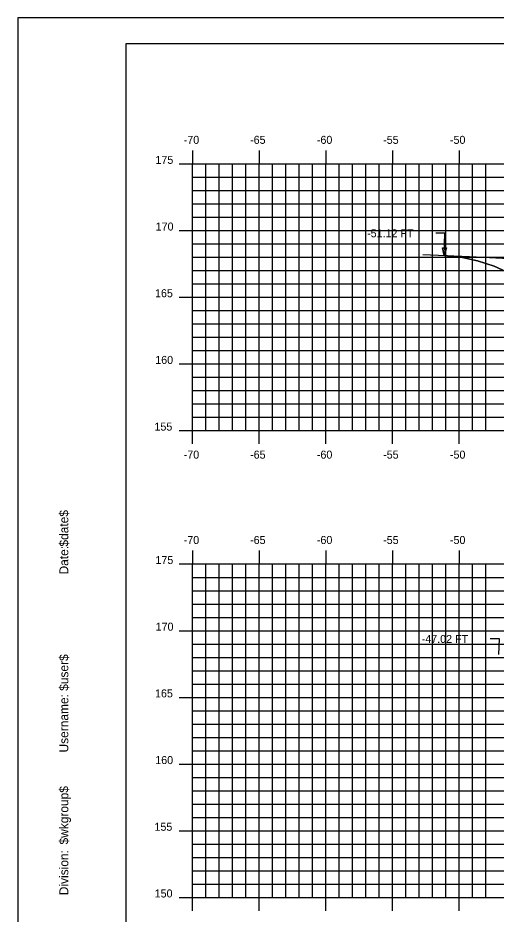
# Model space of a CAD drawing. Extents: x 1141424 to 1141594, y 608981 to 609091.
# Drawn here: x 1141424.2 to 1141460, y 609024.1 to 609091.3 of the extents above; entities that cross this region are included whole.
import ezdxf

# ---------------------------------------------------------------- set-up
doc = ezdxf.new("R2010")
doc.units = 0
for name, color, linetype in [('BORDER', 7, 'Continuous'), ('D_Roadway_SlopeLines', 7, 'Continuous'), ('D_Text_Standard', 7, 'Continuous'), ('H_V ANNOTATION', 7, 'Continuous'), ('MAJOR', 7, 'Continuous'), ('MINOR', 7, 'Continuous'), ('PLOT BOUNDARY', 7, 'Continuous'), ('S_Roadway_Centerline', 7, 'Continuous')]:
    doc.layers.add(name, color=color, linetype=linetype)

msp = doc.modelspace()

# ---------------------------------------------------------------- linework, layer by layer
msp.add_lwpolyline([(1141456.146, 609073.465), (1141457.396, 609073.337), (1141458.646, 609073.068), (1141459.896, 609072.656), (1141461.146, 609072.102), (1141473.145, 609066.102), (1141476.145, 609067.102), (1141483.295, 609069.486), (1141483.296, 609069.486), (1141496.271, 609070.005), (1141507.271, 609070.225), (1141518.271, 609070.005), (1141522.271, 609069.845), (1141529.994, 609067.271), (1141532.994, 609066.271), (1141540.103, 609069.825), (1141541.353, 609070.365), (1141542.603, 609070.736), (1141543.853, 609070.937), (1141545.103, 609070.968)])
at = {"layer": 'BORDER'}
msp.add_lwpolyline([(1141432.271, 608984.335), (1141592.271, 608984.335), (1141592.271, 609089.335), (1141432.271, 609089.335)], close=True, dxfattribs=at)
at = {"layer": 'D_Roadway_SlopeLines'}
msp.add_lwpolyline([(1141473.145, 609066.102), (1141461.146, 609072.102), (1141459.896, 609072.656), (1141458.646, 609073.068), (1141457.396, 609073.337), (1141456.146, 609073.465)], dxfattribs=at)
at = {"layer": 'D_Text_Standard'}
for points in [[(1141456.146, 609073.465), (1141456.186, 609075.131), (1141455.506, 609075.131)], [(1141460.253, 609043.541), (1141460.282, 609044.715), (1141459.602, 609044.715)]]:
    msp.add_lwpolyline(points, dxfattribs=at)
msp.add_lwpolyline([(1141456.146, 609073.465), (1141456.015, 609074.05), (1141456.306, 609074.043)], close=True, dxfattribs=at)
at = {"layer": 'MAJOR'}
for p, q in [((1141437.271, 609081.337), (1141437.271, 609080.335)), ((1141442.271, 609081.337), (1141442.271, 609080.335)), ((1141447.271, 609081.337), (1141447.271, 609080.335)), ((1141452.271, 609081.337), (1141452.271, 609080.335)), ((1141457.271, 609081.337), (1141457.271, 609080.335)), ((1141436.269, 609080.335), (1141437.271, 609080.335)), ((1141437.271, 609080.335), (1141577.271, 609080.335)), ((1141437.271, 609060.335), (1141437.271, 609080.335)), ((1141437.271, 609060.335), (1141437.271, 609080.335)), ((1141437.271, 609080.335), (1141577.271, 609080.335)), ((1141442.271, 609060.335), (1141442.271, 609080.335)), ((1141447.271, 609060.335), (1141447.271, 609080.335)), ((1141452.271, 609060.335), (1141452.271, 609080.335)), ((1141457.271, 609060.335), (1141457.271, 609080.335)), ((1141436.269, 609075.335), (1141437.271, 609075.335)), ((1141437.271, 609075.335), (1141577.271, 609075.335)), ((1141436.269, 609070.335), (1141437.271, 609070.335)), ((1141437.271, 609070.335), (1141577.271, 609070.335)), ((1141436.269, 609065.335), (1141437.271, 609065.335)), ((1141437.271, 609065.335), (1141577.271, 609065.335)), ((1141436.269, 609060.335), (1141437.271, 609060.335)), ((1141437.271, 609060.335), (1141577.271, 609060.335)), ((1141437.271, 609060.335), (1141577.271, 609060.335)), ((1141437.271, 609059.333), (1141437.271, 609060.335)), ((1141442.271, 609059.333), (1141442.271, 609060.335)), ((1141447.271, 609059.333), (1141447.271, 609060.335)), ((1141452.271, 609059.333), (1141452.271, 609060.335)), ((1141457.271, 609059.333), (1141457.271, 609060.335)), ((1141437.271, 609051.337), (1141437.271, 609050.335)), ((1141442.271, 609051.337), (1141442.271, 609050.335)), ((1141447.271, 609051.337), (1141447.271, 609050.335)), ((1141452.271, 609051.337), (1141452.271, 609050.335)), ((1141457.271, 609051.337), (1141457.271, 609050.335)), ((1141436.269, 609050.335), (1141437.271, 609050.335)), ((1141437.271, 609050.335), (1141577.271, 609050.335)), ((1141437.271, 609025.335), (1141437.271, 609050.335)), ((1141437.271, 609025.335), (1141437.271, 609050.335)), ((1141437.271, 609050.335), (1141577.271, 609050.335)), ((1141442.271, 609025.335), (1141442.271, 609050.335)), ((1141447.271, 609025.335), (1141447.271, 609050.335)), ((1141452.271, 609025.335), (1141452.271, 609050.335)), ((1141457.271, 609025.335), (1141457.271, 609050.335)), ((1141436.269, 609045.335), (1141437.271, 609045.335)), ((1141437.271, 609045.335), (1141577.271, 609045.335)), ((1141436.269, 609040.335), (1141437.271, 609040.335)), ((1141437.271, 609040.335), (1141577.271, 609040.335)), ((1141436.269, 609035.335), (1141437.271, 609035.335)), ((1141437.271, 609035.335), (1141577.271, 609035.335)), ((1141436.269, 609030.335), (1141437.271, 609030.335)), ((1141437.271, 609030.335), (1141577.271, 609030.335)), ((1141436.269, 609025.335), (1141437.271, 609025.335)), ((1141437.271, 609025.335), (1141577.271, 609025.335)), ((1141437.271, 609025.335), (1141577.271, 609025.335)), ((1141437.271, 609024.333), (1141437.271, 609025.335)), ((1141442.271, 609024.333), (1141442.271, 609025.335)), ((1141447.271, 609024.333), (1141447.271, 609025.335)), ((1141452.271, 609024.333), (1141452.271, 609025.335)), ((1141457.271, 609024.333), (1141457.271, 609025.335))]:
    msp.add_line(p, q, dxfattribs=at)
at = {"layer": 'MINOR'}
for p, q in [((1141438.271, 609060.335), (1141438.271, 609080.335)), ((1141439.271, 609060.335), (1141439.271, 609080.335)), ((1141440.271, 609060.335), (1141440.271, 609080.335)), ((1141441.271, 609060.335), (1141441.271, 609080.335)), ((1141443.271, 609060.335), (1141443.271, 609080.335)), ((1141444.271, 609060.335), (1141444.271, 609080.335)), ((1141445.271, 609060.335), (1141445.271, 609080.335)), ((1141446.271, 609060.335), (1141446.271, 609080.335)), ((1141448.271, 609060.335), (1141448.271, 609080.335)), ((1141449.271, 609060.335), (1141449.271, 609080.335)), ((1141450.271, 609060.335), (1141450.271, 609080.335)), ((1141451.271, 609060.335), (1141451.271, 609080.335)), ((1141453.271, 609060.335), (1141453.271, 609080.335)), ((1141454.271, 609060.335), (1141454.271, 609080.335)), ((1141455.271, 609060.335), (1141455.271, 609080.335)), ((1141456.271, 609060.335), (1141456.271, 609080.335)), ((1141458.271, 609060.335), (1141458.271, 609080.335)), ((1141459.271, 609060.335), (1141459.271, 609080.335)), ((1141437.271, 609079.335), (1141577.271, 609079.335)), ((1141437.271, 609079.335), (1141438.273, 609079.335)), ((1141437.271, 609078.335), (1141577.271, 609078.335)), ((1141437.271, 609078.335), (1141438.273, 609078.335)), ((1141437.271, 609077.335), (1141577.271, 609077.335)), ((1141437.271, 609077.335), (1141438.273, 609077.335)), ((1141437.271, 609076.335), (1141577.271, 609076.335)), ((1141437.271, 609076.335), (1141438.273, 609076.335)), ((1141437.271, 609074.335), (1141577.271, 609074.335)), ((1141437.271, 609074.335), (1141438.273, 609074.335)), ((1141437.271, 609073.335), (1141577.271, 609073.335)), ((1141437.271, 609073.335), (1141438.273, 609073.335)), ((1141437.271, 609072.335), (1141577.271, 609072.335)), ((1141437.271, 609072.335), (1141438.273, 609072.335)), ((1141437.271, 609071.335), (1141577.271, 609071.335)), ((1141437.271, 609071.335), (1141438.273, 609071.335)), ((1141437.271, 609069.335), (1141577.271, 609069.335)), ((1141437.271, 609069.335), (1141438.273, 609069.335)), ((1141437.271, 609068.335), (1141577.271, 609068.335)), ((1141437.271, 609068.335), (1141438.273, 609068.335)), ((1141437.271, 609067.335), (1141577.271, 609067.335)), ((1141437.271, 609067.335), (1141438.273, 609067.335)), ((1141437.271, 609066.335), (1141577.271, 609066.335)), ((1141437.271, 609066.335), (1141438.273, 609066.335)), ((1141437.271, 609064.335), (1141577.271, 609064.335)), ((1141437.271, 609064.335), (1141438.273, 609064.335)), ((1141437.271, 609063.335), (1141577.271, 609063.335)), ((1141437.271, 609063.335), (1141438.273, 609063.335)), ((1141437.271, 609062.335), (1141577.271, 609062.335)), ((1141437.271, 609062.335), (1141438.273, 609062.335)), ((1141437.271, 609061.335), (1141577.271, 609061.335)), ((1141437.271, 609061.335), (1141438.273, 609061.335)), ((1141438.271, 609025.335), (1141438.271, 609050.335)), ((1141439.271, 609025.335), (1141439.271, 609050.335)), ((1141440.271, 609025.335), (1141440.271, 609050.335)), ((1141441.271, 609025.335), (1141441.271, 609050.335)), ((1141443.271, 609025.335), (1141443.271, 609050.335)), ((1141444.271, 609025.335), (1141444.271, 609050.335)), ((1141445.271, 609025.335), (1141445.271, 609050.335)), ((1141446.271, 609025.335), (1141446.271, 609050.335)), ((1141448.271, 609025.335), (1141448.271, 609050.335)), ((1141449.271, 609025.335), (1141449.271, 609050.335)), ((1141450.271, 609025.335), (1141450.271, 609050.335)), ((1141451.271, 609025.335), (1141451.271, 609050.335)), ((1141453.271, 609025.335), (1141453.271, 609050.335)), ((1141454.271, 609025.335), (1141454.271, 609050.335)), ((1141455.271, 609025.335), (1141455.271, 609050.335)), ((1141456.271, 609025.335), (1141456.271, 609050.335)), ((1141458.271, 609025.335), (1141458.271, 609050.335)), ((1141459.271, 609025.335), (1141459.271, 609050.335)), ((1141437.271, 609049.335), (1141577.271, 609049.335)), ((1141437.271, 609049.335), (1141438.273, 609049.335)), ((1141437.271, 609048.335), (1141577.271, 609048.335)), ((1141437.271, 609048.335), (1141438.273, 609048.335)), ((1141437.271, 609047.335), (1141577.271, 609047.335)), ((1141437.271, 609047.335), (1141438.273, 609047.335)), ((1141437.271, 609046.335), (1141577.271, 609046.335)), ((1141437.271, 609046.335), (1141438.273, 609046.335)), ((1141437.271, 609044.335), (1141577.271, 609044.335)), ((1141437.271, 609044.335), (1141438.273, 609044.335)), ((1141437.271, 609043.335), (1141577.271, 609043.335)), ((1141437.271, 609043.335), (1141438.273, 609043.335)), ((1141437.271, 609042.335), (1141577.271, 609042.335)), ((1141437.271, 609042.335), (1141438.273, 609042.335)), ((1141437.271, 609041.335), (1141577.271, 609041.335)), ((1141437.271, 609041.335), (1141438.273, 609041.335)), ((1141437.271, 609039.335), (1141577.271, 609039.335)), ((1141437.271, 609039.335), (1141438.273, 609039.335)), ((1141437.271, 609038.335), (1141577.271, 609038.335)), ((1141437.271, 609038.335), (1141438.273, 609038.335)), ((1141437.271, 609037.335), (1141577.271, 609037.335)), ((1141437.271, 609037.335), (1141438.273, 609037.335)), ((1141437.271, 609036.335), (1141577.271, 609036.335)), ((1141437.271, 609036.335), (1141438.273, 609036.335)), ((1141437.271, 609034.335), (1141577.271, 609034.335)), ((1141437.271, 609034.335), (1141438.273, 609034.335)), ((1141437.271, 609033.335), (1141577.271, 609033.335)), ((1141437.271, 609033.335), (1141438.273, 609033.335)), ((1141437.271, 609032.335), (1141577.271, 609032.335)), ((1141437.271, 609032.335), (1141438.273, 609032.335)), ((1141437.271, 609031.335), (1141577.271, 609031.335)), ((1141437.271, 609031.335), (1141438.273, 609031.335)), ((1141437.271, 609029.335), (1141577.271, 609029.335)), ((1141437.271, 609029.335), (1141438.273, 609029.335)), ((1141437.271, 609028.335), (1141577.271, 609028.335)), ((1141437.271, 609028.335), (1141438.273, 609028.335)), ((1141437.271, 609027.335), (1141577.271, 609027.335)), ((1141437.271, 609027.335), (1141438.273, 609027.335)), ((1141437.271, 609026.335), (1141577.271, 609026.335)), ((1141437.271, 609026.335), (1141438.273, 609026.335))]:
    msp.add_line(p, q, dxfattribs=at)
at = {"layer": 'PLOT BOUNDARY'}
msp.add_lwpolyline([(1141424.178, 608981.276), (1141594.178, 608981.276), (1141594.178, 609091.276), (1141424.178, 609091.276)], close=True, dxfattribs=at)
at = {"layer": 'S_Roadway_Centerline'}
msp.add_lwpolyline([(1141454.537, 609073.535), (1141458.051, 609073.382), (1141478.858, 609072.336), (1141491.012, 609067.255), (1141491.392, 609067.105), (1141495.226, 609067.794), (1141495.325, 609067.825), (1141495.441, 609067.836), (1141498.174, 609068.166), (1141509.012, 609068.453), (1141509.602, 609068.468), (1141519.951, 609068.08), (1141520.424, 609068.064), (1141520.58, 609068.047), (1141523.884, 609067.752), (1141523.972, 609067.719), (1141527.544, 609066.625), (1141527.941, 609066.801), (1141535.037, 609071.404), (1141544.971, 609070.972), (1141552.331, 609070.764)], dxfattribs=at)

# ---------------------------------------------------------------- texts
at = {"layer": 'BORDER'}
for s, p in [('$date$', (1141427.956, 609051.64)), ('Date:', (1141427.956, 609049.552)), ('$user$', (1141427.956, 609040.827)), ('Username:', (1141427.956, 609036.203)), ('$wkgroup$', (1141427.956, 609029.305)), ('Division:', (1141427.956, 609025.501))]:
    msp.add_text(s, height=0.6696, rotation=90, dxfattribs=at).set_placement(p)
at = {"layer": 'D_Text_Standard'}
for s, p in [('-51.12 FT', (1141450.363, 609074.831)), ('-47.02 FT', (1141454.458, 609044.415))]:
    msp.add_text(s, height=0.6, dxfattribs=at).set_placement(p)
at = {"layer": 'H_V ANNOTATION'}
for s, p in [('-70', (1141436.612, 609081.835)), ('-65', (1141441.588, 609081.835)), ('-60', (1141446.596, 609081.835)), ('-55', (1141451.567, 609081.835)), ('-50', (1141456.575, 609081.835)), ('175', (1141434.491, 609080.335)), ('170', (1141434.507, 609075.335)), ('165', (1141434.46, 609070.335)), ('160', (1141434.476, 609065.335)), ('155', (1141434.417, 609060.335)), ('-70', (1141436.612, 609058.235)), ('-65', (1141441.588, 609058.235)), ('-60', (1141446.596, 609058.235)), ('-55', (1141451.567, 609058.235)), ('-50', (1141456.575, 609058.235)), ('-70', (1141436.612, 609051.835)), ('-65', (1141441.588, 609051.835)), ('-60', (1141446.596, 609051.835)), ('-55', (1141451.567, 609051.835)), ('-50', (1141456.575, 609051.835)), ('175', (1141434.491, 609050.335)), ('170', (1141434.507, 609045.335)), ('165', (1141434.46, 609040.335)), ('160', (1141434.476, 609035.335)), ('155', (1141434.417, 609030.335)), ('150', (1141434.433, 609025.335))]:
    msp.add_text(s, height=0.6, dxfattribs=at).set_placement(p)
at = {"layer": 'MAJOR'}
for p in [(1141437.266, 609060.335), (1141437.266, 609025.335)]:
    msp.add_text('-', height=0.006, dxfattribs=at).set_placement(p)

doc.saveas('drawing.dxf')
